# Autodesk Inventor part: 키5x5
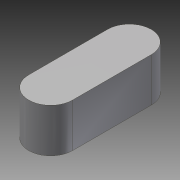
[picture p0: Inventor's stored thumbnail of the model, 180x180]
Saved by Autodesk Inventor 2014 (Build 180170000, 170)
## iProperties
Created: 2011-12
Part Number: 키5x5
Document SubType Name: Modeling
Designer: KYOUNG IL JANG
Density: 7.86 g/cm^3
Material: 강, 연강
Mass: 2.54015 g
Surface Area: 2.9781 cm^2
Volume: 0.323175 cm^3
Appearance: 강철
Author: 석형태
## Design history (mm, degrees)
sketch "스케치1"
  geometry: L1 (34.626, -76.005)-(34.626, -85.005); L2 (39.626, -76.005)-(39.626, -85.005); A1 r 2.5 centre (37.126, -85.005) between (34.626, -85.005) and (39.626, -85.005); A2 r 2.5 centre (37.126, -76.005) between (39.626, -76.005) and (34.626, -76.005); 3 further points
  constraints: 6 point on circle, 4 end point, 4 tangent, 2 centre point, 1 equal radius, 1 vertical alignment
  dimensions: "d0" = 5 diameter of A2; "d1" = 14 distance of point (37.126, -87.505) point (37.126, -73.505)
extrude "돌출1" new body sketch "스케치1" distance "d4" = 5; taper "d5" = 0 deg
node "솔리드1"
